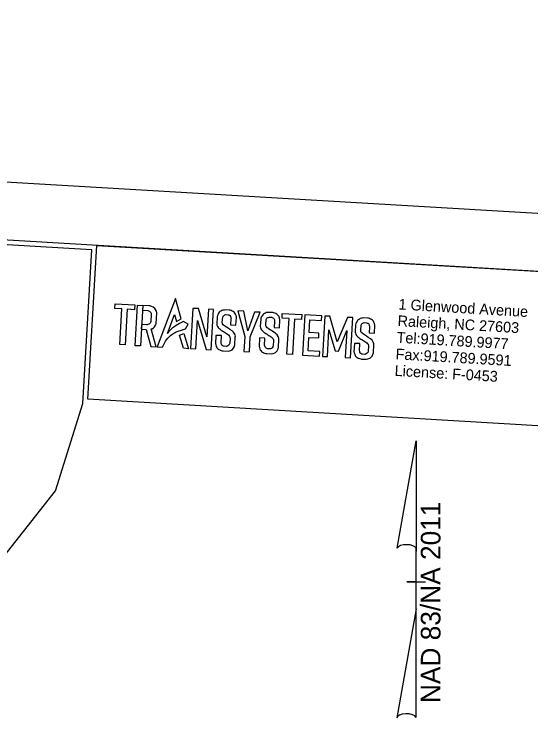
# Model space of a CAD drawing. Extents: x 2012250 to 2014096, y 444445 to 445643.
# Drawn here: x 2013634.6 to 2013858, y 445331.9 to 445643.1 of the extents above; entities that cross this region are included whole.
import ezdxf

# ---------------------------------------------------------------- set-up
doc = ezdxf.new("R2010")
doc.units = 0
for name, color, linetype in [('Old_Level_45', 7, 'Continuous'), ('Old_Level_58', 7, 'Continuous'), ('Sheet Clip Boundary CELL', 7, 'Continuous'), ('Sheet PE Seal CELL', 7, 'Continuous'), ('Sheet Plot Border Outside CELL', 7, 'Continuous'), ('Sheet Professional Seal CELL', 7, 'Continuous'), ('Sheet Profile Grid Minor CELL', 7, 'Continuous')]:
    doc.layers.add(name, color=color, linetype=linetype)

msp = doc.modelspace()

# ---------------------------------------------------------------- linework, layer by layer
at = {"layer": 'Old_Level_45'}
msp.add_lwpolyline([(2014069.67, 445519.6), (2012572.27, 445607.87), (2012510.48, 444559.69), (2014007.88, 444471.42)], close=True, dxfattribs=at)
at = {"layer": 'Old_Level_58'}
msp.add_lwpolyline([(2013670.27, 445543.15), (2013869.97, 445531.38), (2013866.05, 445464.8), (2013666.34, 445476.57)], close=True, dxfattribs=at)
at = {"layer": 'Sheet Clip Boundary CELL'}
msp.add_lwpolyline([(2013668.15, 445541.27), (2012675.35, 445599.79), (2012666.5, 445450.87), (2012644.05, 445070.04), (2012629.92, 444830.46), (2012620.01, 444659.47), (2012673.15, 444619.9), (2012617.31, 444617.99), (2012613.72, 444555.61), (2014006.01, 444473.54), (2014041.96, 445083.42), (2013915.76, 445258.44), (2013612.37, 445329.9), (2013615.96, 445390.93), (2013652.41, 445436.93), (2013664.23, 445474.69)], close=True, dxfattribs=at)
at = {"layer": 'Sheet Plot Border Outside CELL'}
msp.add_lwpolyline([(2012334.32, 444545.03), (2014031.37, 444445), (2014096.1, 445543.09), (2012399.05, 445643.13)], close=True, dxfattribs=at)
at = {"layer": 'Sheet Professional Seal CELL'}
for p, q in [((2013800.18, 445412.2), (2013808.38, 445458.55)), ((2013808.43, 445458.55), (2013808.38, 445458.55)), ((2013808.43, 445458.55), (2013808.38, 445458.55)), ((2013808.43, 445458.55), (2013808.43, 445410.75)), ((2013808.43, 445385.95), (2013808.43, 445412.15)), ((2013808.43, 445410.75), (2013808.43, 445412.1)), ((2013804.43, 445397.55), (2013804.38, 445397.55)), ((2013807.98, 445397.55), (2013804.43, 445397.55)), ((2013804.48, 445397.55), (2013812.48, 445397.55)), ((2013808.43, 445385.95), (2013800.08, 445338.7)), ((2013808.48, 445338.9), (2013808.43, 445385.95))]:
    msp.add_line(p, q, dxfattribs=at)
for centre, start_param, end_param in [((2013804.32, 445411.7), 0.216388, 2.908219), ((2013804.32, 445338.53), 0.201328, 3.141593)]:
    msp.add_ellipse(centre, major_axis=(4.23, -0.03), ratio=0.461098, start_param=start_param, end_param=end_param, dxfattribs=at)
at = {"layer": 'Sheet Profile Grid Minor CELL'}
for points in [[(2013704.33, 445520.19), (2013696.42, 445499.28), (2013698.64, 445499.16), (2013699.03, 445499.98), (2013699.67, 445501.11), (2013700.02, 445501.72), (2013700.42, 445502.23), (2013700.99, 445502.96), (2013701.34, 445503.41), (2013701.75, 445503.78), (2013702.15, 445504.14), (2013702.66, 445504.61), (2013703.09, 445504.86), (2013703.52, 445505.16), (2013704.1, 445505.45), (2013704.61, 445505.7), (2013705.85, 445506.2), (2013706.88, 445506.55), (2013708.55, 445507.01), (2013709.81, 445509.09), (2013707.69, 445510.17), (2013706.01, 445509.38), (2013704.58, 445508.56), (2013703.56, 445507.82), (2013703.01, 445507.42), (2013702.44, 445506.89), (2013701.88, 445506.35), (2013701.45, 445505.95), (2013701.04, 445505.33), (2013700.81, 445504.98), (2013703.93, 445513.19), (2013704.75, 445510.25), (2013706.72, 445511.39)], [(2013678.18, 445517.88), (2013686.63, 445517.39), (2013686.51, 445515.32), (2013683.41, 445515.5), (2013682.52, 445500.1), (2013680.17, 445500.24), (2013681.07, 445515.73), (2013678.1, 445515.91)], [(2013687.78, 445517.3), (2013690.1, 445517.17), (2013689.08, 445499.63), (2013686.77, 445499.77)], [(2013689.98, 445515.09), (2013692.36, 445514.95), (2013692.66, 445514.88), (2013693.05, 445514.7), (2013693.36, 445514.46), (2013693.58, 445514.17), (2013693.71, 445513.84), (2013693.82, 445513.57), (2013693.78, 445512.99), (2013693.65, 445510.51), (2013693.57, 445510.18), (2013693.46, 445509.74), (2013693.31, 445509.46), (2013693.09, 445509.21), (2013692.81, 445509.01), (2013692.38, 445508.88), (2013692.05, 445508.86), (2013691.72, 445508.84), (2013689.62, 445508.95), (2013689.51, 445506.85), (2013691.61, 445506.73), (2013693.55, 445499.44), (2013695.97, 445499.33), (2013693.76, 445507.01), (2013694.15, 445507.12), (2013694.71, 445507.49), (2013695.23, 445507.99), (2013695.61, 445508.6), (2013695.87, 445509.22), (2013695.86, 445509.41), (2013696.17, 445513.97), (2013696.01, 445514.72), (2013695.69, 445515.42), (2013695.31, 445515.92), (2013694.64, 445516.43), (2013693.98, 445516.69), (2013693.31, 445516.96), (2013692.91, 445516.98), (2013690.1, 445517.17)], [(2013711.86, 445515.92), (2013710.85, 445498.49), (2013713.08, 445498.36), (2013713.79, 445510.62), (2013717.51, 445498.08), (2013719.76, 445497.97), (2013720.77, 445515.45), (2013718.59, 445515.57), (2013717.9, 445503.61), (2013714.21, 445515.79)], [(2013728.16, 445508.78), (2013730.47, 445508.65), (2013730.67, 445512.12), (2013730.52, 445512.83), (2013730.27, 445513.44), (2013730, 445513.85), (2013729.65, 445514.22), (2013729.23, 445514.53), (2013728.81, 445514.73), (2013728.81, 445514.73), (2013728.36, 445514.95), (2013727.89, 445515.1), (2013727.57, 445515.19), (2013725.83, 445515.26), (2013725.29, 445515.2), (2013724.83, 445515.15), (2013724.36, 445514.94), (2013723.94, 445514.75), (2013723.53, 445514.49), (2013723.2, 445514.2), (2013722.94, 445513.84), (2013722.72, 445513.46), (2013722.43, 445512.78), (2013722.35, 445512.27), (2013722.16, 445509.11), (2013722.25, 445508.62), (2013722.45, 445508.12), (2013722.71, 445507.69), (2013722.99, 445507.36), (2013723.42, 445506.99), (2013723.85, 445506.62), (2013724.12, 445506.38), (2013724.59, 445506.13), (2013725.06, 445505.87), (2013725.43, 445505.6), (2013725.86, 445505.29), (2013726.37, 445504.99), (2013726.79, 445504.75), (2013727.2, 445504.41), (2013727.49, 445504.09), (2013727.73, 445503.84), (2013727.85, 445503.35), (2013727.93, 445503.05), (2013727.76, 445500.82), (2013727.57, 445500.34), (2013727.3, 445499.94), (2013726.96, 445499.67), (2013726.59, 445499.53), (2013726.25, 445499.48), (2013725.29, 445499.51), (2013724.97, 445499.62), (2013724.65, 445499.83), (2013724.34, 445500.05), (2013724.21, 445500.39), (2013724.09, 445500.73), (2013723.99, 445501.01), (2013724.14, 445504.11), (2013721.81, 445504.22), (2013721.63, 445500.52), (2013721.73, 445500.23), (2013721.95, 445499.35), (2013722.11, 445499.05), (2013722.34, 445498.72), (2013722.7, 445498.32), (2013722.99, 445498.11), (2013723.42, 445497.9), (2013723.57, 445497.83), (2013723.99, 445497.62), (2013724.52, 445497.54), (2013724.91, 445497.48), (2013727.05, 445497.4), (2013727.65, 445497.51), (2013728.5, 445497.83), (2013728.78, 445497.94), (2013729.45, 445498.7), (2013729.83, 445499.46), (2013730.03, 445500.16), (2013730.18, 445503.58), (2013730.2, 445504.05), (2013730.09, 445504.44), (2013729.92, 445504.8), (2013729.42, 445505.59), (2013728.75, 445506.19), (2013727.81, 445506.82), (2013727.09, 445507.31), (2013725.68, 445508.16), (2013724.96, 445508.77), (2013724.65, 445509.21), (2013724.59, 445509.5), (2013724.53, 445509.78), (2013724.72, 445512.21), (2013724.86, 445512.45), (2013725, 445512.7), (2013725.19, 445512.84), (2013725.43, 445513.03), (2013725.69, 445513.12), (2013725.96, 445513.21), (2013726.1, 445513.17), (2013726.12, 445513.24), (2013727.08, 445513.17), (2013727.35, 445513.05), (2013727.62, 445512.92), (2013727.89, 445512.8), (2013728.01, 445512.6), (2013728.18, 445512.31), (2013728.25, 445512.03), (2013728.33, 445511.74), (2013728.3, 445511.44)], [(2013733.79, 445514.64), (2013731.25, 445514.79), (2013734.23, 445503.71), (2013733.87, 445497.18), (2013736.26, 445497.05), (2013736.61, 445503.53), (2013740.91, 445514.26), (2013738.41, 445514.34), (2013735.62, 445506.15)], [(2013747, 445507.69), (2013749.31, 445507.55), (2013749.51, 445511.02), (2013749.36, 445511.74), (2013749.11, 445512.35), (2013748.84, 445512.75), (2013748.49, 445513.12), (2013748.07, 445513.43), (2013747.65, 445513.63), (2013747.65, 445513.63), (2013747.21, 445513.85), (2013746.73, 445514), (2013746.41, 445514.1), (2013744.67, 445514.17), (2013744.13, 445514.11), (2013743.67, 445514.06), (2013743.2, 445513.84), (2013742.78, 445513.66), (2013742.37, 445513.4), (2013742.04, 445513.1), (2013741.78, 445512.75), (2013741.56, 445512.37), (2013741.27, 445511.69), (2013741.19, 445511.18), (2013741, 445508.01), (2013741.09, 445507.53), (2013741.29, 445507.03), (2013741.55, 445506.6), (2013741.83, 445506.27), (2013742.26, 445505.9), (2013742.69, 445505.52), (2013742.96, 445505.29), (2013743.43, 445505.03), (2013743.9, 445504.78), (2013744.27, 445504.51), (2013744.7, 445504.19), (2013745.21, 445503.9), (2013745.63, 445503.65), (2013746.04, 445503.31), (2013746.33, 445503), (2013746.57, 445502.75), (2013746.69, 445502.26), (2013746.77, 445501.96), (2013746.6, 445499.72), (2013746.41, 445499.25), (2013746.14, 445498.85), (2013745.8, 445498.58), (2013745.43, 445498.43), (2013745.09, 445498.38), (2013744.13, 445498.42), (2013743.81, 445498.53), (2013743.49, 445498.74), (2013743.18, 445498.95), (2013743.05, 445499.3), (2013742.93, 445499.64), (2013742.84, 445499.91), (2013742.98, 445503.02), (2013740.65, 445503.13), (2013740.47, 445499.43), (2013740.57, 445499.14), (2013740.79, 445498.26), (2013740.95, 445497.96), (2013741.18, 445497.63), (2013741.54, 445497.23), (2013741.83, 445497.02), (2013742.26, 445496.81), (2013742.41, 445496.74), (2013742.83, 445496.53), (2013743.36, 445496.44), (2013743.75, 445496.38), (2013745.89, 445496.31), (2013746.49, 445496.42), (2013747.34, 445496.74), (2013747.62, 445496.85), (2013748.29, 445497.6), (2013748.67, 445498.37), (2013748.87, 445499.07), (2013749.02, 445502.49), (2013749.04, 445502.96), (2013748.93, 445503.34), (2013748.76, 445503.71), (2013748.26, 445504.5), (2013747.59, 445505.1), (2013746.65, 445505.73), (2013745.93, 445506.22), (2013744.52, 445507.07), (2013743.8, 445507.67), (2013743.5, 445508.11), (2013743.43, 445508.4), (2013743.37, 445508.69), (2013743.56, 445511.11), (2013743.7, 445511.36), (2013743.84, 445511.61), (2013744.03, 445511.75), (2013744.27, 445511.93), (2013744.53, 445512.02), (2013744.8, 445512.12), (2013744.94, 445512.08), (2013744.96, 445512.15), (2013745.92, 445512.08), (2013746.19, 445511.95), (2013746.46, 445511.83), (2013746.73, 445511.7), (2013746.85, 445511.5), (2013747.02, 445511.21), (2013747.09, 445510.93), (2013747.17, 445510.65), (2013747.14, 445510.35)], [(2013750.52, 445513.68), (2013758.97, 445513.19), (2013758.85, 445511.12), (2013755.75, 445511.3), (2013754.85, 445495.9), (2013752.51, 445496.04), (2013753.41, 445511.54), (2013750.44, 445511.71)], [(2013767.56, 445512.68), (2013760.19, 445513.11), (2013759.18, 445495.71), (2013766.64, 445495.28), (2013766.75, 445497.25), (2013761.72, 445497.54), (2013762.05, 445503.37), (2013766.26, 445503.13), (2013766.38, 445505.2), (2013762.14, 445505.45), (2013762.46, 445510.93), (2013767.46, 445510.64)], [(2013774.29, 445501.42), (2013771.12, 445512.54), (2013768.91, 445512.57), (2013767.97, 445495.13), (2013770.07, 445495.02), (2013770.7, 445506.68), (2013773.44, 445497.52), (2013774.78, 445497.4), (2013778.38, 445506.34), (2013777.74, 445494.64), (2013780.01, 445494.51), (2013780.97, 445511.9), (2013778.68, 445512.03)], [(2013788.07, 445505.3), (2013790.37, 445505.17), (2013790.57, 445508.64), (2013790.42, 445509.36), (2013790.18, 445509.96), (2013789.9, 445510.37), (2013789.55, 445510.74), (2013789.13, 445511.05), (2013788.71, 445511.25), (2013788.71, 445511.25), (2013788.27, 445511.47), (2013787.79, 445511.62), (2013787.48, 445511.72), (2013785.73, 445511.79), (2013785.2, 445511.73), (2013784.74, 445511.67), (2013784.26, 445511.46), (2013783.84, 445511.28), (2013783.43, 445511.01), (2013783.11, 445510.72), (2013782.84, 445510.37), (2013782.63, 445509.99), (2013782.33, 445509.31), (2013782.25, 445508.79), (2013782.06, 445505.63), (2013782.15, 445505.15), (2013782.35, 445504.64), (2013782.61, 445504.22), (2013782.89, 445503.89), (2013783.32, 445503.52), (2013783.75, 445503.14), (2013784.02, 445502.91), (2013784.49, 445502.65), (2013784.96, 445502.4), (2013785.34, 445502.12), (2013785.76, 445501.81), (2013786.27, 445501.51), (2013786.69, 445501.27), (2013787.1, 445500.93), (2013787.39, 445500.62), (2013787.63, 445500.37), (2013787.75, 445499.88), (2013787.83, 445499.57), (2013787.66, 445497.34), (2013787.47, 445496.87), (2013787.2, 445496.46), (2013786.86, 445496.19), (2013786.5, 445496.05), (2013786.15, 445496), (2013785.19, 445496.04), (2013784.87, 445496.15), (2013784.56, 445496.36), (2013784.24, 445496.57), (2013784.12, 445496.91), (2013784, 445497.26), (2013783.9, 445497.53), (2013784.05, 445500.64), (2013781.71, 445500.75), (2013781.53, 445497.04), (2013781.64, 445496.76), (2013781.85, 445495.88), (2013782.01, 445495.58), (2013782.25, 445495.24), (2013782.6, 445494.85), (2013782.9, 445494.64), (2013783.32, 445494.43), (2013783.47, 445494.35), (2013783.89, 445494.15), (2013784.42, 445494.06), (2013784.81, 445494), (2013786.95, 445493.93), (2013787.55, 445494.03), (2013788.4, 445494.36), (2013788.69, 445494.47), (2013789.35, 445495.22), (2013789.74, 445495.99), (2013789.93, 445496.69), (2013790.08, 445500.11), (2013790.1, 445500.58), (2013789.99, 445500.96), (2013789.82, 445501.33), (2013789.33, 445502.12), (2013788.65, 445502.71), (2013787.71, 445503.35), (2013787, 445503.84), (2013785.58, 445504.69), (2013784.86, 445505.29), (2013784.56, 445505.73), (2013784.5, 445506.02), (2013784.44, 445506.31), (2013784.63, 445508.73), (2013784.76, 445508.98), (2013784.9, 445509.23), (2013785.09, 445509.37), (2013785.33, 445509.55), (2013785.6, 445509.64), (2013785.86, 445509.73), (2013786.01, 445509.7), (2013786.03, 445509.77), (2013786.98, 445509.7), (2013787.25, 445509.57), (2013787.52, 445509.45), (2013787.79, 445509.32), (2013787.91, 445509.12), (2013788.08, 445508.83), (2013788.16, 445508.55), (2013788.23, 445508.27), (2013788.21, 445507.97)], [(2013706.01, 445504.36), (2013707.97, 445505.01), (2013709.85, 445498.45), (2013707.76, 445498.65)]]:
    msp.add_lwpolyline(points, close=True, dxfattribs=at)

# ---------------------------------------------------------------- texts
at = {"layer": 'Sheet PE Seal CELL'}
for s, p in [('1 Glenwood Avenue', (2013800.71, 445515.46)), ('Raleigh, NC 27603', (2013800.29, 445508.28)), ('Tel:919.789.9977 ', (2013799.86, 445501.09)), ('Fax:919.789.9591', (2013799.44, 445493.91)), ('License: F-0453', (2013799.02, 445486.73))]:
    msp.add_text(s, height=4.6576, rotation=356.6264, dxfattribs=at).set_placement(p)
at = {"layer": 'Sheet Professional Seal CELL'}
msp.add_text('NAD 83/NA 2011', height=8.5, rotation=90, dxfattribs=at).set_placement((2013818.95, 445345.12))

doc.saveas('drawing.dxf')
